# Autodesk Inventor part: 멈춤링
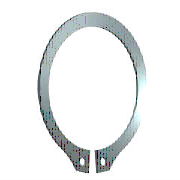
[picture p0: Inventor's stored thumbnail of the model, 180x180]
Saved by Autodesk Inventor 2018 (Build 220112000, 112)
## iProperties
IsCustomPart: 1
Created: 2012-02
Part Number: 멈춤링
Material: 강철, 연강
Description: 리테이닝 링(C형)
Document SubType Name: Modeling
Standard: KS B 1336
Designer: mduedu
Standards Organization: KS
Language: ko-KR
Size Designation: 20 x 1.2
Categories: <MemberInstance><Categories><Category DisplayName="샤프트 부품" InternalName="7f7aeb1f-a693-4053-b835-cee3144e0d98" Mnemonic="SHFT"><Category DisplayName="써클립" Inter
Density: 7.85 g/cm^3
Appearance: 노란색
Mass: 1.66335 g
Surface Area: 5.4075 cm^2
Volume: 0.211892 cm^3
Author: mduedu
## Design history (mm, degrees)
sketch "스케치1"
  geometry: L1 (-6, 0)-(6, 0) reference; L2 (0, 20.189)-(0, -80.536) reference; L3 (-48.09, 0)-(48.09, 0) reference; L4 (-0.5, -19.487)-(-0.5, -23.387); L5 (-0.5, -6.54)-(-0.5, -13.29); L6 (-2.795, 2.7)-(3.672, 2.7); L7 (0.5, -6.54)-(0.5, -13.29); L8 (0.5, -19.487)-(0.5, -23.387); C1 r 1 at (-2, -21.219); C2 r 1 at (2, -21.219); A1 r 9.5 centre (0, -10) between (0.5, -19.487) and (-0.5, -19.487); A2 r 12.025 centre (0, -9.325) between (5.071, -20.228) and (-5.071, -20.228); A3 r 13.396 centre (0, -10) between (-2.351, -23.188) and (-0.5, -23.387); A4 r 2 centre (-2, -21.219) between (-3.957, -21.631) and (-2.351, -23.188); A5 r 2 centre (-5.915, -22.042) between (-3.957, -21.631) and (-5.071, -20.228); A6 r 2 centre (5.915, -22.042) between (5.071, -20.228) and (3.957, -21.631); A7 r 2 centre (2, -21.219) between (2.351, -23.188) and (3.957, -21.631); A8 r 13.396 centre (0, -10) between (0.5, -23.387) and (2.351, -23.188)
  constraints: 16 point on circle, 12 end point, 10 centre point, 9 symmetric about line, 5 point on line, 4 tangent, 3 coincident, 2 horizontal, 1 perpendicular, 1 vertical, 5 other
  dimensions: "d0" = 19 diameter of A1 (= ND); "d1" = 3.9 distance of L4.end L4.start (= SRB2); "d6" = 0.5 distance between parallel lines of L2 L5 (= 0.25 x SD5); "d7" = 2.7 distance between parallel lines of L6 L3 (= SRB1); "d8" = 0.675 distance of A1.centre A2.centre (= 0.25 x SRB1); "d9" = 2 radius of A4 (= SD5); "d10" = 2 radius of A5 (= SD5); "d11" = 1.5 distance from line of L4 A4.centre (= 0.75 x SD5); "d12" = 2 diameter of C1 (= SD5); "d13" = 2 diameter of C2 (= SD5); "d14" = 10 distance from line of A1.centre L1 (= 0.5 x WD)
extrude "본체" new body sketch "스케치1" distance "d2" = 1.2 (= SD); taper "d3" = 0 deg
workaxis "Work Axis1"
workplane "Work Plane1"
body "Solid1"
other parameters: "SD" = 1.2 [user parameter; used in 1 equation term], "SRB1" = 2.7 [user parameter; used in 2 equation terms], "ND" = 19 [user parameter; used in 1 equation term], "SRB2" = 3.9 [user parameter; used in 1 equation term], "SD5" = 2 [user parameter; used in 6 equation terms], "d15" = 0, "d16" = 0, "d17" = 0, "d41" = 0, "d42" = 0, "SD3" = 18.5 [user parameter], "WDMAX" = 21 [user parameter]
